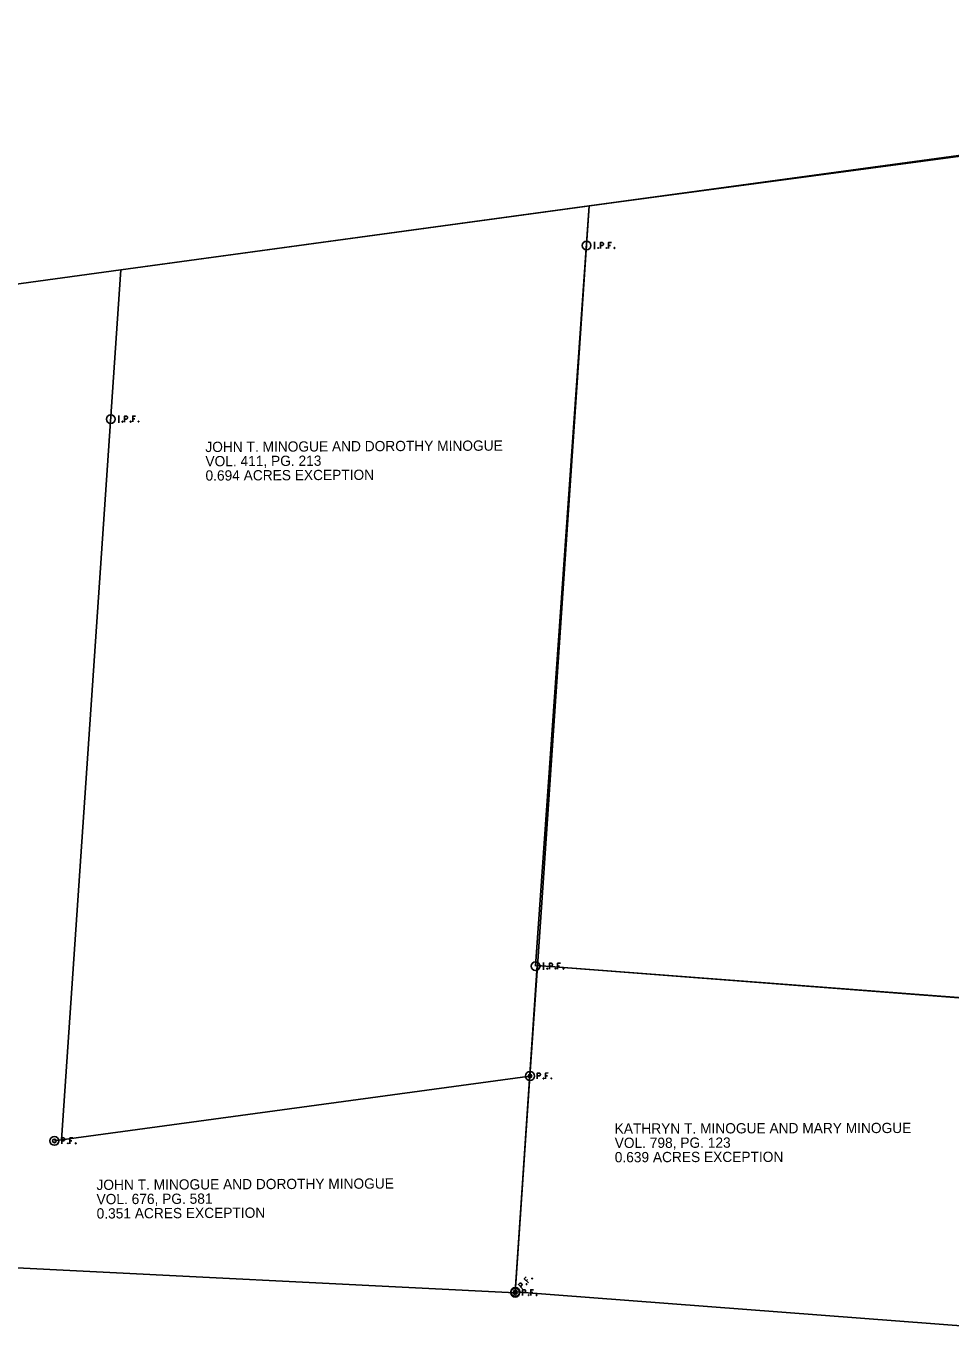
# Model space of a CAD drawing. Extents: x 1532954 to 1577849, y 698998 to 706606.
# Drawn here: x 1573939.4 to 1574191.7, y 702465.7 to 702820.6 of the extents above; entities that cross this region are included whole.
import ezdxf

# ---------------------------------------------------------------- set-up
doc = ezdxf.new("R2010")
doc.units = 0
doc.layers.add('SC_Scratch3', color=7, linetype='Continuous')

msp = doc.modelspace()

# ---------------------------------------------------------------- linework, layer by layer
at = {"layer": 'SC_Scratch3'}
for p, q in [((1574452.7, 702820.6), (1573965.28, 702754.1)), ((1574093.03, 702771.53), (1574452.7, 702820.6)), ((1574093.03, 702771.53), (1574452.82, 702819.72)), ((1574093.03, 702771.53), (1573965.28, 702754.1)), ((1574078.39, 702564.15), (1574093.03, 702771.53)), ((1574078.9, 702564.11), (1574093.03, 702771.53)), ((1573965.28, 702754.1), (1573929.71, 702749.25)), ((1573949.1, 702516.75), (1573965.28, 702754.1)), ((1573965.28, 702754.1), (1573949.1, 702516.75)), ((1574078.84, 702564.33), (1574072.85, 702475.29)), ((1574076.86, 702534.18), (1574078.9, 702564.11)), ((1574432.88, 702537.28), (1574078.83, 702564.35)), ((1574204.33, 702554.74), (1574078.84, 702564.33)), ((1574076.86, 702534.18), (1573949.1, 702516.75)), ((1573949.1, 702516.75), (1574076.86, 702534.18)), ((1574072.83, 702475.08), (1574076.86, 702534.18)), ((1573949.1, 702516.75), (1573947.12, 702516.48)), ((1573911.57, 702483.1), (1574072.83, 702475.08)), ((1574072.85, 702475.29), (1574198.03, 702465.72))]:
    msp.add_line(p, q, dxfattribs=at)
for points in [[(1574094.31, 702761.53), (1574094.66, 702761.53)], [(1574094.31, 702759.93), (1574094.67, 702759.93)], [(1574094.49, 702759.93), (1574094.48, 702761.53)], [(1574095.45, 702760.15), (1574095.5, 702760.15), (1574095.54, 702760.12), (1574095.57, 702760.07), (1574095.57, 702760.01), (1574095.54, 702759.96), (1574095.5, 702759.93), (1574095.45, 702759.93), (1574095.41, 702759.96), (1574095.38, 702760.01), (1574095.38, 702760.07), (1574095.41, 702760.12), (1574095.45, 702760.15)], [(1574096.05, 702759.94), (1574096.05, 702761.54), (1574096.58, 702761.54), (1574096.63, 702761.53), (1574096.71, 702761.5), (1574096.74, 702761.48), (1574096.77, 702761.45), (1574096.82, 702761.39), (1574096.85, 702761.33), (1574096.88, 702761.22), (1574096.88, 702761.07), (1574096.87, 702761.02), (1574096.84, 702760.95), (1574096.8, 702760.86), (1574096.76, 702760.82), (1574096.72, 702760.8), (1574096.67, 702760.77), (1574096.58, 702760.76), (1574096.05, 702760.76)], [(1574097.7, 702760.16), (1574097.75, 702760.16), (1574097.78, 702760.13), (1574097.82, 702760.08), (1574097.82, 702760.02), (1574097.78, 702759.97), (1574097.75, 702759.94), (1574097.7, 702759.94), (1574097.66, 702759.97), (1574097.63, 702760.02), (1574097.63, 702760.08), (1574097.66, 702760.13), (1574097.7, 702760.16)], [(1574099.06, 702761.55), (1574098.3, 702761.55), (1574098.3, 702759.95)], [(1574098.3, 702760.77), (1574098.84, 702760.77)], [(1574099.85, 702760.17), (1574099.9, 702760.17), (1574099.93, 702760.14), (1574099.97, 702760.09), (1574099.97, 702760.03), (1574099.93, 702759.98), (1574099.9, 702759.95), (1574099.85, 702759.95), (1574099.81, 702759.98), (1574099.78, 702760.03), (1574099.78, 702760.09), (1574099.81, 702760.14), (1574099.85, 702760.17)], [(1573964.51, 702714.17), (1573964.86, 702714.17)], [(1573964.69, 702712.57), (1573964.69, 702714.17)], [(1573965.65, 702712.79), (1573965.71, 702712.79), (1573965.74, 702712.76), (1573965.77, 702712.71), (1573965.77, 702712.65), (1573965.74, 702712.6), (1573965.71, 702712.57), (1573965.65, 702712.57), (1573965.62, 702712.6), (1573965.59, 702712.65), (1573965.59, 702712.71), (1573965.62, 702712.76), (1573965.65, 702712.79)], [(1573966.26, 702712.58), (1573966.25, 702714.18), (1573966.78, 702714.18), (1573966.84, 702714.17), (1573966.91, 702714.14), (1573966.95, 702714.12), (1573966.98, 702714.09), (1573967.02, 702714.03), (1573967.06, 702713.97), (1573967.08, 702713.87), (1573967.08, 702713.71), (1573967.07, 702713.66), (1573967.05, 702713.59), (1573967, 702713.5), (1573966.96, 702713.46), (1573966.93, 702713.44), (1573966.87, 702713.41), (1573966.78, 702713.4), (1573966.25, 702713.4)], [(1573967.9, 702712.8), (1573967.95, 702712.8), (1573967.99, 702712.77), (1573968.02, 702712.72), (1573968.02, 702712.66), (1573967.99, 702712.61), (1573967.96, 702712.58), (1573967.9, 702712.58), (1573967.87, 702712.61), (1573967.83, 702712.66), (1573967.83, 702712.72), (1573967.87, 702712.77), (1573967.9, 702712.8)], [(1573969.26, 702714.19), (1573968.5, 702714.19), (1573968.51, 702712.59)], [(1573968.5, 702713.41), (1573969.04, 702713.41)], [(1573970.05, 702712.81), (1573970.1, 702712.81), (1573970.14, 702712.78), (1573970.17, 702712.73), (1573970.17, 702712.67), (1573970.14, 702712.62), (1573970.11, 702712.59), (1573970.05, 702712.59), (1573970.02, 702712.62), (1573969.98, 702712.67), (1573969.98, 702712.73), (1573970.02, 702712.78), (1573970.05, 702712.81)], [(1573964.52, 702712.57), (1573964.87, 702712.57)], [(1574080.4, 702564.95), (1574080.75, 702564.96)], [(1574080.58, 702563.35), (1574080.58, 702564.95)], [(1574081.54, 702563.57), (1574081.59, 702563.57), (1574081.63, 702563.55), (1574081.66, 702563.5), (1574081.66, 702563.43), (1574081.63, 702563.38), (1574081.59, 702563.36), (1574081.54, 702563.36), (1574081.51, 702563.38), (1574081.47, 702563.43), (1574081.47, 702563.5), (1574081.51, 702563.55), (1574081.54, 702563.57)], [(1574082.15, 702563.36), (1574082.14, 702564.96), (1574082.67, 702564.96), (1574082.73, 702564.95), (1574082.8, 702564.92), (1574082.84, 702564.9), (1574082.87, 702564.87), (1574082.91, 702564.81), (1574082.95, 702564.75), (1574082.97, 702564.64), (1574082.97, 702564.49), (1574082.96, 702564.44), (1574082.94, 702564.37), (1574082.89, 702564.28), (1574082.85, 702564.24), (1574082.82, 702564.22), (1574082.76, 702564.19), (1574082.67, 702564.18), (1574082.14, 702564.18)], [(1574083.79, 702563.58), (1574083.84, 702563.58), (1574083.88, 702563.55), (1574083.91, 702563.5), (1574083.91, 702563.44), (1574083.88, 702563.39), (1574083.84, 702563.36), (1574083.79, 702563.36), (1574083.75, 702563.39), (1574083.72, 702563.44), (1574083.72, 702563.5), (1574083.75, 702563.55), (1574083.79, 702563.58)], [(1574085.15, 702564.96), (1574084.39, 702564.96), (1574084.39, 702563.36)], [(1574084.39, 702564.18), (1574084.93, 702564.18)], [(1574085.94, 702563.58), (1574085.99, 702563.58), (1574086.03, 702563.56), (1574086.06, 702563.51), (1574086.06, 702563.44), (1574086.03, 702563.39), (1574085.99, 702563.37), (1574085.94, 702563.37), (1574085.9, 702563.39), (1574085.87, 702563.44), (1574085.87, 702563.51), (1574085.9, 702563.56), (1574085.94, 702563.58)], [(1574080.4, 702563.35), (1574080.76, 702563.36)], [(1574078.86, 702533.39), (1574078.85, 702534.99), (1574079.38, 702535), (1574079.44, 702534.98), (1574079.51, 702534.96), (1574079.55, 702534.93), (1574079.58, 702534.91), (1574079.62, 702534.85), (1574079.66, 702534.78), (1574079.68, 702534.68), (1574079.68, 702534.53), (1574079.67, 702534.48), (1574079.65, 702534.4), (1574079.61, 702534.32), (1574079.56, 702534.28), (1574079.53, 702534.25), (1574079.47, 702534.23), (1574079.39, 702534.21), (1574078.86, 702534.21)], [(1574078.86, 702533.39), (1574078.85, 702534.99), (1574079.38, 702535), (1574079.44, 702534.98), (1574079.51, 702534.96), (1574079.55, 702534.93), (1574079.58, 702534.91), (1574079.62, 702534.85), (1574079.66, 702534.78), (1574079.68, 702534.68), (1574079.68, 702534.53), (1574079.67, 702534.48), (1574079.65, 702534.4), (1574079.61, 702534.32), (1574079.56, 702534.28), (1574079.53, 702534.25), (1574079.47, 702534.23), (1574079.39, 702534.21), (1574078.86, 702534.21)], [(1574080.5, 702533.62), (1574080.56, 702533.62), (1574080.59, 702533.59), (1574080.62, 702533.54), (1574080.62, 702533.48), (1574080.59, 702533.43), (1574080.56, 702533.4), (1574080.5, 702533.4), (1574080.47, 702533.43), (1574080.44, 702533.48), (1574080.44, 702533.54), (1574080.47, 702533.59), (1574080.5, 702533.62)], [(1574080.5, 702533.62), (1574080.56, 702533.62), (1574080.59, 702533.59), (1574080.62, 702533.54), (1574080.62, 702533.48), (1574080.59, 702533.43), (1574080.56, 702533.4), (1574080.5, 702533.4), (1574080.47, 702533.43), (1574080.44, 702533.48), (1574080.44, 702533.54), (1574080.47, 702533.59), (1574080.5, 702533.62)], [(1574081.86, 702535.01), (1574081.1, 702535), (1574081.11, 702533.4)], [(1574081.86, 702535.01), (1574081.1, 702535), (1574081.11, 702533.4)], [(1574081.1, 702534.22), (1574081.65, 702534.23)], [(1574081.1, 702534.22), (1574081.65, 702534.23)], [(1574082.65, 702533.63), (1574082.71, 702533.63), (1574082.74, 702533.6), (1574082.77, 702533.55), (1574082.77, 702533.49), (1574082.74, 702533.44), (1574082.71, 702533.41), (1574082.65, 702533.41), (1574082.62, 702533.44), (1574082.59, 702533.49), (1574082.59, 702533.55), (1574082.62, 702533.6), (1574082.65, 702533.63)], [(1574082.65, 702533.63), (1574082.71, 702533.63), (1574082.74, 702533.6), (1574082.77, 702533.55), (1574082.77, 702533.49), (1574082.74, 702533.44), (1574082.71, 702533.41), (1574082.65, 702533.41), (1574082.62, 702533.44), (1574082.59, 702533.49), (1574082.59, 702533.55), (1574082.62, 702533.6), (1574082.65, 702533.63)], [(1573949.12, 702515.69), (1573949.11, 702517.29), (1573949.64, 702517.3), (1573949.7, 702517.28), (1573949.78, 702517.26), (1573949.81, 702517.23), (1573949.84, 702517.21), (1573949.89, 702517.15), (1573949.92, 702517.08), (1573949.94, 702516.98), (1573949.94, 702516.83), (1573949.93, 702516.78), (1573949.91, 702516.7), (1573949.87, 702516.62), (1573949.82, 702516.58), (1573949.79, 702516.55), (1573949.74, 702516.53), (1573949.65, 702516.51), (1573949.12, 702516.51)], [(1573950.76, 702515.92), (1573950.82, 702515.92), (1573950.85, 702515.89), (1573950.88, 702515.84), (1573950.89, 702515.78), (1573950.85, 702515.73), (1573950.82, 702515.7), (1573950.76, 702515.7), (1573950.73, 702515.73), (1573950.7, 702515.78), (1573950.7, 702515.84), (1573950.73, 702515.89), (1573950.76, 702515.92)], [(1573952.12, 702517.31), (1573951.36, 702517.3), (1573951.37, 702515.7)], [(1573951.37, 702516.52), (1573951.91, 702516.53)], [(1573952.91, 702515.93), (1573952.97, 702515.93), (1573953, 702515.9), (1573953.03, 702515.85), (1573953.03, 702515.79), (1573953, 702515.74), (1573952.97, 702515.71), (1573952.91, 702515.71), (1573952.88, 702515.74), (1573952.85, 702515.79), (1573952.85, 702515.85), (1573952.88, 702515.9), (1573952.91, 702515.93)], [(1574075.81, 702479.4), (1574075.27, 702478.86), (1574076.41, 702477.74)], [(1574075.83, 702478.31), (1574076.21, 702478.7)], [(1574077.35, 702478.98), (1574077.38, 702479.02), (1574077.43, 702479.02), (1574077.48, 702479.01), (1574077.53, 702478.97), (1574077.54, 702478.91), (1574077.54, 702478.87), (1574077.5, 702478.83), (1574077.46, 702478.82), (1574077.4, 702478.84), (1574077.35, 702478.88), (1574077.34, 702478.94), (1574077.35, 702478.98)], [(1574074.82, 702476.14), (1574073.69, 702477.27), (1574074.06, 702477.65), (1574074.11, 702477.68), (1574074.18, 702477.71), (1574074.22, 702477.72), (1574074.26, 702477.72), (1574074.34, 702477.71), (1574074.41, 702477.69), (1574074.49, 702477.63), (1574074.6, 702477.53), (1574074.63, 702477.48), (1574074.67, 702477.41), (1574074.7, 702477.32), (1574074.7, 702477.26), (1574074.69, 702477.22), (1574074.67, 702477.17), (1574074.62, 702477.09), (1574074.24, 702476.72)], [(1574074.83, 702474.29), (1574074.83, 702475.89), (1574075.35, 702475.89), (1574075.41, 702475.88), (1574075.49, 702475.86), (1574075.52, 702475.83), (1574075.55, 702475.81), (1574075.6, 702475.74), (1574075.63, 702475.68), (1574075.65, 702475.58), (1574075.65, 702475.43), (1574075.64, 702475.38), (1574075.62, 702475.3), (1574075.58, 702475.21), (1574075.53, 702475.18), (1574075.5, 702475.15), (1574075.45, 702475.12), (1574075.36, 702475.11), (1574074.83, 702475.11)], [(1574075.83, 702477.46), (1574075.87, 702477.5), (1574075.91, 702477.5), (1574075.97, 702477.49), (1574076.01, 702477.44), (1574076.03, 702477.39), (1574076.02, 702477.34), (1574075.98, 702477.31), (1574075.94, 702477.3), (1574075.88, 702477.31), (1574075.84, 702477.36), (1574075.82, 702477.42), (1574075.83, 702477.46)], [(1574077.83, 702475.9), (1574077.07, 702475.9), (1574077.08, 702474.3)], [(1574077.08, 702475.12), (1574077.62, 702475.12)], [(1574076.47, 702474.51), (1574076.53, 702474.51), (1574076.56, 702474.49), (1574076.6, 702474.44), (1574076.6, 702474.37), (1574076.56, 702474.32), (1574076.53, 702474.3), (1574076.48, 702474.3), (1574076.44, 702474.32), (1574076.41, 702474.37), (1574076.41, 702474.44), (1574076.44, 702474.49), (1574076.47, 702474.51)], [(1574078.62, 702474.52), (1574078.68, 702474.52), (1574078.71, 702474.5), (1574078.75, 702474.45), (1574078.75, 702474.38), (1574078.71, 702474.33), (1574078.68, 702474.31), (1574078.62, 702474.31), (1574078.59, 702474.33), (1574078.56, 702474.38), (1574078.56, 702474.45), (1574078.59, 702474.5), (1574078.62, 702474.52)]]:
    msp.add_lwpolyline(points, dxfattribs=at)
for centre, radius in [((1574092.29, 702760.72), 1.2), ((1573962.5, 702713.36), 1.2), ((1574078.39, 702564.15), 1.2), ((1574076.86, 702534.18), 1.2), ((1574076.86, 702534.18), 1.2), ((1574076.86, 702534.18), 0.495), ((1574076.86, 702534.18), 0.495), ((1573947.12, 702516.48), 1.2), ((1573947.12, 702516.48), 0.495), ((1574072.83, 702475.08), 1.2), ((1574072.85, 702475.29), 1.2), ((1574072.83, 702475.08), 0.495), ((1574072.85, 702475.29), 0.495)]:
    msp.add_circle(centre, radius, dxfattribs=at)

# ---------------------------------------------------------------- texts
for s, rotation, p in [('JOHN T. MINOGUE AND DOROTHY MINOGUE', 0.2687, (1573988.31, 702704.39)), ('VOL. 411, PG. 213', 0.2687, (1573988.33, 702700.49)), ('0.694 ACRES EXCEPTION', 0.2687, (1573988.35, 702696.59)), ('KATHRYN T. MINOGUE AND MARY MINOGUE', 0.1305, (1574099.96, 702518.45)), ('VOL. 798, PG. 123', 0.1305, (1574099.97, 702514.55)), ('0.639 ACRES EXCEPTION', 0.1305, (1574099.98, 702510.65)), ('JOHN T. MINOGUE AND DOROTHY MINOGUE', 0.2687, (1573958.61, 702503.1)), ('VOL. 676, PG. 581', 0.2687, (1573958.63, 702499.2)), ('0.351 ACRES EXCEPTION', 0.2687, (1573958.65, 702495.3))]:
    msp.add_text(s, height=2.8, rotation=rotation, dxfattribs=at).set_placement(p)

doc.saveas('drawing.dxf')
